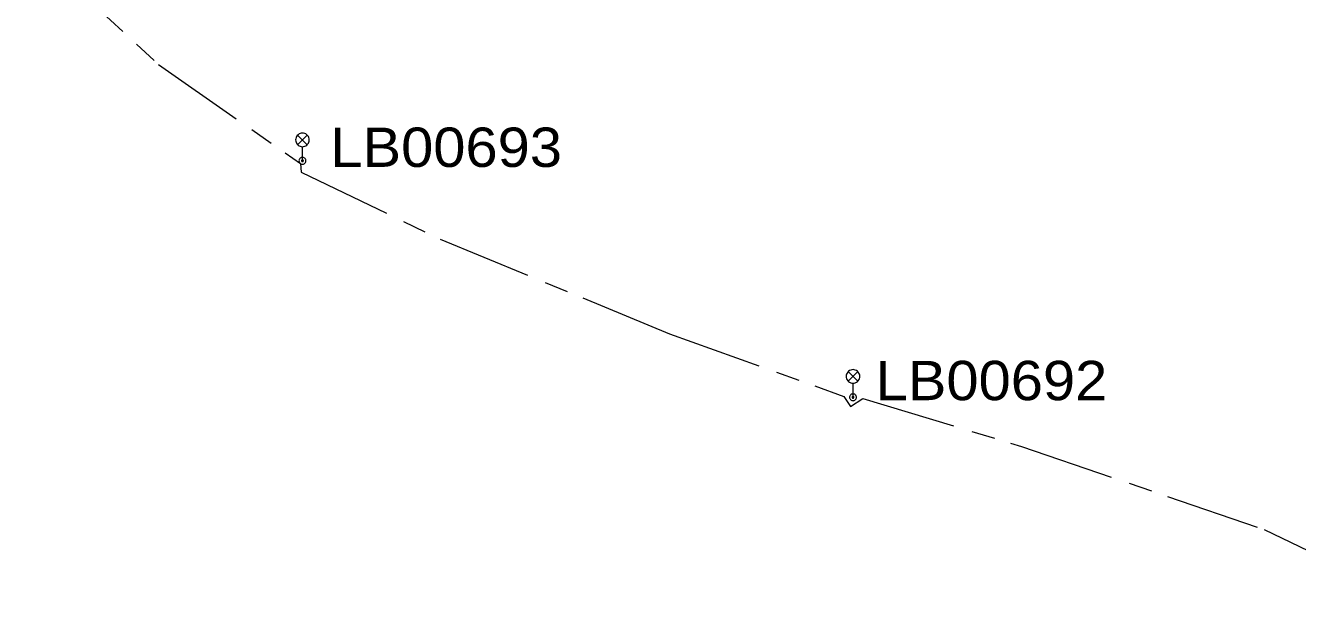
# Model space of a CAD drawing. Extents: x -688049 to -687261, y -973611 to -973038.
# Drawn here: x -687831.4 to -687761.3, y -973286.5 to -973255 of the extents above; entities that cross this region are included whole.
import ezdxf

# ---------------------------------------------------------------- set-up
doc = ezdxf.new("R2010")
doc.units = 0
doc.header["$LTSCALE"] = 0.87
doc.linetypes.add('LONG_DASH_SHORT_DASH', pattern=[9.9, 6, -1.2, 1.5, -1.2])
doc.layers.add('1', color=7, linetype='Continuous', lineweight=13)

msp = doc.modelspace()

# ---------------------------------------------------------------- linework, layer by layer
at = {"layer": '1'}
for p, q in [((-687816.415, -973261.045), (-687815.885, -973261.575)), ((-687816.415, -973261.575), (-687815.885, -973261.045)), ((-687816.15, -973262.46), (-687816.15, -973261.685)), ((-687786.085, -973274.075), (-687785.555, -973274.605)), ((-687786.085, -973274.605), (-687785.555, -973274.075)), ((-687785.82, -973275.49), (-687785.82, -973274.715))]:
    msp.add_line(p, q, dxfattribs=at)
at = {"layer": '1', "linetype": 'LONG_DASH_SHORT_DASH'}
for points in [[(-687831.41, -973250.219), (-687829.88, -973251.79), (-687824.08, -973257.16), (-687817.111, -973262.026)], [(-687817.111, -973262.026), (-687816.26, -973262.62), (-687816.22, -973263.08), (-687808.57, -973266.78), (-687800.711, -973270.019), (-687795.93, -973271.99), (-687787.93, -973274.862)], [(-687787.93, -973274.862), (-687786.32, -973275.44), (-687785.96, -973276), (-687785.27, -973275.55), (-687777.136, -973278.019)], [(-687777.136, -973278.019), (-687776.54, -973278.2), (-687768.499, -973280.955)], [(-687768.499, -973280.955), (-687763.17, -973282.78), (-687755.512, -973286.469)]]:
    msp.add_lwpolyline(points, dxfattribs=at)
at = {"layer": '1'}
for points in [[(-687815.775, -973261.31), (-687815.781, -973261.245), (-687815.798, -973261.182), (-687815.825, -973261.122), (-687815.863, -973261.069), (-687815.909, -973261.023), (-687815.962, -973260.985), (-687816.022, -973260.958), (-687816.085, -973260.941), (-687816.15, -973260.935), (-687816.215, -973260.941), (-687816.278, -973260.958), (-687816.338, -973260.985), (-687816.391, -973261.023), (-687816.437, -973261.069), (-687816.475, -973261.122), (-687816.502, -973261.182), (-687816.519, -973261.245), (-687816.525, -973261.31), (-687816.519, -973261.375), (-687816.502, -973261.438), (-687816.475, -973261.497), (-687816.437, -973261.551), (-687816.391, -973261.597), (-687816.338, -973261.635), (-687816.278, -973261.662), (-687816.215, -973261.679), (-687816.15, -973261.685), (-687816.085, -973261.679), (-687816.022, -973261.662), (-687815.962, -973261.635), (-687815.909, -973261.597), (-687815.863, -973261.551), (-687815.825, -973261.497), (-687815.798, -973261.438), (-687815.781, -973261.375)], [(-687815.96, -973262.46), (-687815.963, -973262.427), (-687815.971, -973262.395), (-687815.985, -973262.365), (-687816.004, -973262.338), (-687816.028, -973262.314), (-687816.055, -973262.295), (-687816.085, -973262.281), (-687816.117, -973262.273), (-687816.15, -973262.27), (-687816.183, -973262.273), (-687816.215, -973262.281), (-687816.245, -973262.295), (-687816.272, -973262.314), (-687816.296, -973262.338), (-687816.315, -973262.365), (-687816.329, -973262.395), (-687816.337, -973262.427), (-687816.34, -973262.46), (-687816.337, -973262.493), (-687816.329, -973262.525), (-687816.315, -973262.555), (-687816.296, -973262.582), (-687816.272, -973262.606), (-687816.245, -973262.625), (-687816.215, -973262.639), (-687816.183, -973262.647), (-687816.15, -973262.65), (-687816.117, -973262.647), (-687816.085, -973262.639), (-687816.055, -973262.625), (-687816.028, -973262.606), (-687816.004, -973262.582), (-687815.985, -973262.555), (-687815.971, -973262.525), (-687815.963, -973262.493)], [(-687816.1, -973262.46), (-687816.101, -973262.451), (-687816.103, -973262.443), (-687816.107, -973262.435), (-687816.112, -973262.428), (-687816.118, -973262.422), (-687816.125, -973262.417), (-687816.133, -973262.413), (-687816.141, -973262.411), (-687816.15, -973262.41), (-687816.159, -973262.411), (-687816.167, -973262.413), (-687816.175, -973262.417), (-687816.182, -973262.422), (-687816.188, -973262.428), (-687816.193, -973262.435), (-687816.197, -973262.443), (-687816.199, -973262.451), (-687816.2, -973262.46), (-687816.199, -973262.469), (-687816.197, -973262.477), (-687816.193, -973262.485), (-687816.188, -973262.492), (-687816.182, -973262.498), (-687816.175, -973262.503), (-687816.167, -973262.507), (-687816.159, -973262.509), (-687816.15, -973262.51), (-687816.141, -973262.509), (-687816.133, -973262.507), (-687816.125, -973262.503), (-687816.118, -973262.498), (-687816.112, -973262.492), (-687816.107, -973262.485), (-687816.103, -973262.477), (-687816.101, -973262.469)], [(-687785.445, -973274.34), (-687785.451, -973274.275), (-687785.468, -973274.212), (-687785.495, -973274.153), (-687785.533, -973274.099), (-687785.579, -973274.053), (-687785.633, -973274.015), (-687785.692, -973273.988), (-687785.755, -973273.971), (-687785.82, -973273.965), (-687785.885, -973273.971), (-687785.948, -973273.988), (-687786.008, -973274.015), (-687786.061, -973274.053), (-687786.107, -973274.099), (-687786.145, -973274.153), (-687786.172, -973274.212), (-687786.189, -973274.275), (-687786.195, -973274.34), (-687786.189, -973274.405), (-687786.172, -973274.468), (-687786.145, -973274.528), (-687786.107, -973274.581), (-687786.061, -973274.627), (-687786.008, -973274.665), (-687785.948, -973274.692), (-687785.885, -973274.709), (-687785.82, -973274.715), (-687785.755, -973274.709), (-687785.692, -973274.692), (-687785.633, -973274.665), (-687785.579, -973274.627), (-687785.533, -973274.581), (-687785.495, -973274.528), (-687785.468, -973274.468), (-687785.451, -973274.405)], [(-687785.63, -973275.49), (-687785.633, -973275.457), (-687785.641, -973275.425), (-687785.655, -973275.395), (-687785.674, -973275.368), (-687785.698, -973275.344), (-687785.725, -973275.325), (-687785.755, -973275.311), (-687785.787, -973275.303), (-687785.82, -973275.3), (-687785.853, -973275.303), (-687785.885, -973275.311), (-687785.915, -973275.325), (-687785.942, -973275.344), (-687785.966, -973275.368), (-687785.985, -973275.395), (-687785.999, -973275.425), (-687786.007, -973275.457), (-687786.01, -973275.49), (-687786.007, -973275.523), (-687785.999, -973275.555), (-687785.985, -973275.585), (-687785.966, -973275.612), (-687785.942, -973275.636), (-687785.915, -973275.655), (-687785.885, -973275.669), (-687785.853, -973275.677), (-687785.82, -973275.68), (-687785.787, -973275.677), (-687785.755, -973275.669), (-687785.725, -973275.655), (-687785.698, -973275.636), (-687785.674, -973275.612), (-687785.655, -973275.585), (-687785.641, -973275.555), (-687785.633, -973275.523)], [(-687785.77, -973275.49), (-687785.771, -973275.481), (-687785.773, -973275.473), (-687785.777, -973275.465), (-687785.782, -973275.458), (-687785.788, -973275.452), (-687785.795, -973275.447), (-687785.803, -973275.443), (-687785.811, -973275.441), (-687785.82, -973275.44), (-687785.829, -973275.441), (-687785.837, -973275.443), (-687785.845, -973275.447), (-687785.852, -973275.452), (-687785.858, -973275.458), (-687785.863, -973275.465), (-687785.867, -973275.473), (-687785.869, -973275.481), (-687785.87, -973275.49), (-687785.869, -973275.499), (-687785.867, -973275.507), (-687785.863, -973275.515), (-687785.858, -973275.522), (-687785.852, -973275.528), (-687785.845, -973275.533), (-687785.837, -973275.537), (-687785.829, -973275.539), (-687785.82, -973275.54), (-687785.811, -973275.539), (-687785.803, -973275.537), (-687785.795, -973275.533), (-687785.788, -973275.528), (-687785.782, -973275.522), (-687785.777, -973275.515), (-687785.773, -973275.507), (-687785.771, -973275.499)]]:
    msp.add_lwpolyline(points, close=True, dxfattribs=at)

# ---------------------------------------------------------------- texts
at = {"layer": '1', "width": 1.1}
for s, p in [('LB00693', (-687814.614, -973262.799)), ('LB00692', (-687784.574, -973275.65))]:
    msp.add_text(s, height=2.167, dxfattribs=at).set_placement(p)

doc.saveas('drawing.dxf')
